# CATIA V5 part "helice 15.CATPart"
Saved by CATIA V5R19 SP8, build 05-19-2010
Part number: helice 15
Bounding box of the stored display mesh (mm): x -17.321 to 17.321, y -30 to 195, z -10 to 20
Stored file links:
  G:\EU_thinkMotion\CFAO_2010\MMS_groupe2\MMS_groupe2\A reprendre\splanchenault\Planchenault\helice 15.CATPart
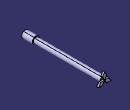
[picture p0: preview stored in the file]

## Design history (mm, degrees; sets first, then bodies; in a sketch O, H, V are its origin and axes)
Body1 (main body)
  Sketch1 on yz-plane, origin (0, 0, 0), H (0, 1, 0), V (0, 0, 1)
    line L1 (0, 0) -> (-30, 0)
    line L2 (-30, 0) -> (-30, 10)
    line L3 (-30, 10) -> (0, 10)
    line L4 (0, 10) -> (0, 7.5)
    line L5 (0, 7.5) -> (190, 7.5)
    line L6 (190, 7.5) -> (190, 0)
    point P6 (190, 0)
    line L7 (190, 0) -> (0, 0)
    length L6 = 7.5
    horizontal: L1 H, L3 H, L5 H, L7 H
    vertical: L2 V, L4 V, L6 V
    coincidence: P6 H
  Shaft1: profile Sketch1, axis Sketch1.L1, angle 360
  Sketch2 on face of Shaft1 from Sketch1.L6, origin (0, 190, 0), H (-1, 0, 0), V (0, 0, 1)
    construction line L1 (19.3649, -11.1803) -> (-19.3649, 11.1803)
    axis line L2 (-19.3649, -11.1803) -> (18.75, 10.8253)
    line L3 (0, 0) -> (5.7735, 10)
    point P5 (5.7735, 10)
    line L4 (5.7735, 10) -> (0, 20)
    point P6 (0, 20)
    line L5 (0, 20) -> (-5.7735, 10)
    point P7 (-5.7735, 10)
    line L6 (0, 0) -> (-5.7735, 10)
    point P8 (-17.3205, -10)
    point P9 (-5.7735, -10)
    line L7 (-5.7735, -10) -> (-17.3205, -10)
    point P10 (-11.547, 0)
    line L8 (-17.3205, -10) -> (-11.547, 0)
    point P11 (0, 0)
    line L9 (0, 0) -> (-11.547, 0)
    line L10 (0, 0) -> (-5.7735, -10)
    point P12 (5.7735, -10)
    point P13 (17.3205, -10)
    line L11 (17.3205, -10) -> (5.7735, -10)
    point P14 (11.547, 0)
    line L12 (11.547, 0) -> (17.3205, -10)
    point P15 (0, 0)
    line L13 (0, 0) -> (11.547, 0)
    line L14 (0, 0) -> (5.7735, -10)
    angle L1 V = 60
    angle L2 V = 60
    coincidence: L2 O, P6 V, O P11, O P15, P11 P15
    perpendicularity: L3 L1, L4 L2
    parallelism: L5 L3, L6 L4
    symmetry: P6 P8 L1, P5 P9 L1, L4 L7 L1, P7 P10 L1, L5 L8 L1, O P11 L1, L6 L9 L1, L3 L10 L1, P7 P12 L2, P6 P13 L2, L5 L11 L2, P5 P14 L2, L4 L12 L2, O P15 L2, L3 L13 L2, L6 L14 L2
  Pad1: profile Sketch2, direction (0, 1, 0), length 5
